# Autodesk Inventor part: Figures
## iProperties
Created: 2001-11
Part Number: Figures
Document SubType Name: Modeling
Designer: Renu Muthoo
Density: 1 g/cm^3
Control State: 0
Master: False
Checked Out: False
Shininess: 65.0
Angle Display Precision: 2
Document Length Units: 11269
Document Angle Units: 11279
Document Time Units: 11290
Document Mass Units: 11283
Document Length Units Precision: 3
Document Angle Units Precision: 2
Compacted: False
Density: 0.0
Volumn: 0.0
Area: 0.0
PropertySet Name: Model Information
Author: Renu Muthoo
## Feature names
1. Extrusion1
2. Extrusion2
3. Extrusion3
4. Hole1
